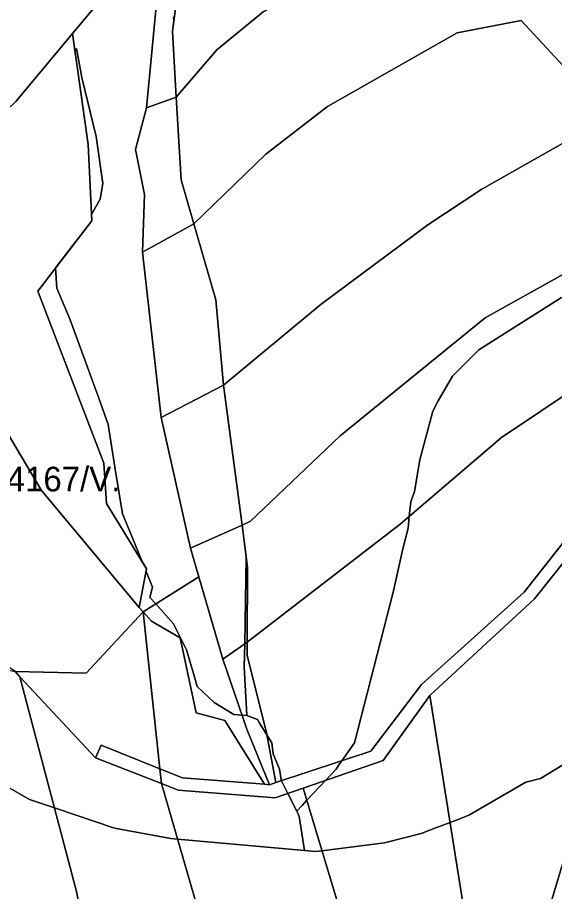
# Model space of a CAD drawing. Extents: x -502026 to -497664, y -1143484 to -1138019.
# Drawn here: x -499892.7 to -499718.6, y -1138993.9 to -1138710.6 of the extents above; entities that cross this region are included whole.
import ezdxf

# ---------------------------------------------------------------- set-up
doc = ezdxf.new("R2010")
doc.units = 0
for name, color, linetype in [('37', 7, 'Continuous'), ('43', 7, 'Continuous'), ('55', 7, 'Continuous'), ('62', 7, 'Continuous'), ('7', 7, 'Continuous')]:
    doc.layers.add(name, color=color, linetype=linetype)

msp = doc.modelspace()

# ---------------------------------------------------------------- linework, layer by layer
at = {"layer": '37'}
for points in [[(-499624.19, -1138623.47), (-499697.07, -1138662.14), (-499715.47, -1138666.65), (-499778.38, -1138690.2), (-499812.98, -1138708.74), (-499828.03, -1138721.09), (-499841.22, -1138736.39), (-499842.46, -1138715.08), (-499840.59, -1138700.98), (-499826.55, -1138669.42), (-499786.16, -1138649.02), (-499741.11, -1138634.19), (-499707.24, -1138629.85), (-499653.4, -1138608.06), (-499638.95, -1138599.65)], [(-499584.72, -1138701.93), (-499647.14, -1138735.95), (-499688.61, -1138754.3), (-499700.38, -1138742.85), (-499700.56, -1138742.65), (-499729.36, -1138711.56), (-499750.17, -1138715.52), (-499792.14, -1138739.41), (-499812.14, -1138754.89), (-499835.52, -1138777.51), (-499839.65, -1138763.23), (-499841.22, -1138736.39), (-499828.03, -1138721.09), (-499812.98, -1138708.74), (-499778.38, -1138690.2), (-499715.47, -1138666.65), (-499697.07, -1138662.14), (-499624.19, -1138623.47), (-499605.59, -1138653.48), (-499597.17, -1138655.53), (-499535.12, -1138622.58), (-499555.94, -1138687.68), (-499558.61, -1138690.15), (-499573.23, -1138697.97)], [(-499700.56, -1138742.65), (-499742.16, -1138766.28), (-499759.69, -1138777.83), (-499794.21, -1138803.47), (-499825.87, -1138829.77), (-499828.42, -1138802.06), (-499835.52, -1138777.51), (-499812.14, -1138754.89), (-499792.14, -1138739.41), (-499750.17, -1138715.52), (-499729.36, -1138711.56)], [(-499688.61, -1138754.3), (-499686.59, -1138756.26), (-499686.17, -1138759.35), (-499683.91, -1138775.8), (-499683.87, -1138776.05), (-499741.05, -1138807.99), (-499788.02, -1138846.17), (-499817.14, -1138873.87), (-499819.87, -1138875.19), (-499825.87, -1138829.77), (-499794.21, -1138803.47), (-499759.69, -1138777.83), (-499742.16, -1138766.28), (-499700.56, -1138742.65), (-499700.38, -1138742.85)], [(-499677.97, -1138812.1), (-499697.49, -1138821.17), (-499735.75, -1138846.76), (-499768.66, -1138874.79), (-499818.19, -1138913.08), (-499818.08, -1138888.78), (-499819.87, -1138875.19), (-499817.14, -1138873.87), (-499788.02, -1138846.17), (-499741.05, -1138807.99), (-499683.87, -1138776.05)], [(-499672.73, -1138826.19), (-499728.38, -1138896.85), (-499761.65, -1138926.83), (-499778.12, -1138948.42), (-499808.88, -1138958.63), (-499811.95, -1138942.47), (-499818.21, -1138917.28), (-499818.19, -1138913.08), (-499768.66, -1138874.79), (-499735.75, -1138846.76), (-499697.49, -1138821.17), (-499677.97, -1138812.1)], [(-499692.22, -1139026.74), (-499706.34, -1139073.94), (-499740.09, -1139074.1), (-499740.7, -1139066.99), (-499704.64, -1138947.61), (-499698.3, -1138985.62)]]:
    msp.add_lwpolyline(points, close=True, dxfattribs=at)
at = {"layer": '43'}
msp.add_lwpolyline([(-499902.54, -1138656.11), (-499880.58, -1138648.07), (-499846.81, -1138644), (-499831.31, -1138625.84), (-499798.18, -1138628.43), (-499780.24, -1138632.61), (-499752.34, -1138635.48), (-499793.82, -1138640.76), (-499822.42, -1138652.25), (-499843.96, -1138678.89), (-499874.85, -1138715.81), (-499893.13, -1138737.65)], dxfattribs=at)
for points in [[(-499840.59, -1138700.98), (-499842.46, -1138715.08), (-499841.22, -1138736.39), (-499850.82, -1138739.83), (-499847.44, -1138703.59), (-499843.96, -1138678.89), (-499822.42, -1138652.25), (-499838.76, -1138687.12)], [(-499850.82, -1138739.83), (-499854.46, -1138753.4), (-499851.53, -1138767.96), (-499852.16, -1138786.6), (-499846.16, -1138840.24), (-499836.59, -1138882.65), (-499833.88, -1138891.94), (-499851.98, -1138903.25), (-499853.25, -1138901.83), (-499850.82, -1138889.32), (-499863.78, -1138868.14), (-499864.68, -1138855.11), (-499886.12, -1138799.3), (-499868.63, -1138776.44), (-499869.78, -1138751.79), (-499874.85, -1138715.81), (-499843.96, -1138678.89), (-499847.44, -1138703.59)], [(-499835.52, -1138777.51), (-499852.16, -1138786.6), (-499851.53, -1138767.96), (-499854.46, -1138753.4), (-499850.82, -1138739.83), (-499841.22, -1138736.39), (-499839.65, -1138763.23)], [(-499825.87, -1138829.77), (-499846.16, -1138840.24), (-499852.16, -1138786.6), (-499835.52, -1138777.51), (-499828.42, -1138802.06)], [(-499819.87, -1138875.19), (-499836.59, -1138882.65), (-499846.16, -1138840.24), (-499825.87, -1138829.77)], [(-499818.19, -1138913.08), (-499826.12, -1138918.58), (-499833.88, -1138891.94), (-499836.59, -1138882.65), (-499819.87, -1138875.19), (-499818.08, -1138888.78)], [(-499826.12, -1138918.58), (-499818.34, -1138941.27), (-499810.93, -1138959.31), (-499812.62, -1138959.18), (-499825.48, -1138938.52), (-499834.8, -1138935.97), (-499839.91, -1138911.67), (-499849.23, -1138906.3), (-499851.98, -1138903.25), (-499833.88, -1138891.94)], [(-499808.88, -1138958.63), (-499810.93, -1138959.31), (-499818.34, -1138941.27), (-499826.12, -1138918.58), (-499818.19, -1138913.08), (-499818.21, -1138917.28), (-499811.95, -1138942.47)]]:
    msp.add_lwpolyline(points, close=True, dxfattribs=at)
at = {"layer": '55'}
msp.add_lwpolyline([(-499714.87, -1138886.33), (-499725.1, -1138899.04), (-499758.97, -1138930.35), (-499774.17, -1138951.42), (-499800.05, -1138960.4), (-499809.14, -1138963.55), (-499840.61, -1138961.03), (-499846.04, -1138958.92), (-499846.55, -1138954.13), (-499839.14, -1138957.13), (-499812.62, -1138959.18), (-499810.93, -1138959.31), (-499808.88, -1138958.63), (-499778.12, -1138948.42), (-499761.65, -1138926.83), (-499728.38, -1138896.85), (-499672.73, -1138826.19)], dxfattribs=at)
at = {"layer": '62'}
for points in [[(-499842.09, -1138710.37), (-499842, -1138711.59), (-499842.46, -1138715.08), (-499841.22, -1138736.39), (-499839.65, -1138763.23), (-499835.52, -1138777.51), (-499828.42, -1138802.06), (-499825.87, -1138829.77), (-499819.87, -1138875.19), (-499818.5, -1138885.58), (-499819.02, -1138913.65), (-499819.16, -1138921.12), (-499818.31, -1138936.87), (-499819.89, -1138936.73), (-499822.56, -1138936.5), (-499828.94, -1138932.62), (-499834.44, -1138927.5), (-499835.65, -1138923.27), (-499837.84, -1138915.62), (-499842.09, -1138907.12), (-499847.89, -1138900.69), (-499849.75, -1138898.62), (-499848.91, -1138895.25), (-499850.99, -1138890.18), (-499850.82, -1138889.32), (-499852.4, -1138886.73), (-499855.55, -1138879.07), (-499858.66, -1138871.5), (-499861, -1138857), (-499863.34, -1138842.5), (-499866.31, -1138834), (-499875.66, -1138808.62), (-499879.91, -1138798.37), (-499880.34, -1138791.74), (-499868.63, -1138776.44), (-499868.72, -1138774.48), (-499865.91, -1138769.5), (-499865.03, -1138764.37), (-499867.16, -1138749.12), (-499871.84, -1138730), (-499873.53, -1138720.62), (-499874.09, -1138721.24), (-499874.85, -1138715.81), (-499893.13, -1138737.65)], [(-499716.34, -1138801.37), (-499743.09, -1138818.37), (-499751.59, -1138826.87), (-499756.28, -1138834.87), (-499757.97, -1138838.25), (-499762.22, -1138854), (-499763.94, -1138864.25), (-499765.19, -1138867.62), (-499765.66, -1138872.24), (-499766.06, -1138876.12), (-499767.75, -1138882.87), (-499770.72, -1138896.5), (-499783.47, -1138945.75), (-499787.51, -1138951.54), (-499788.47, -1138952.91), (-499789.41, -1138954.25), (-499792.81, -1138957.89), (-499798.86, -1138964.36), (-499800.42, -1138966.01), (-499802.16, -1138967.87), (-499805.05, -1138962.13), (-499806.01, -1138960.22), (-499807.1, -1138958.04), (-499807.25, -1138957.75), (-499807.69, -1138954.25), (-499809.81, -1138949.25), (-499810.25, -1138945.75), (-499811.81, -1138943.19), (-499814.32, -1138939.09), (-499814.91, -1138938.12), (-499818.31, -1138936.87), (-499819.16, -1138921.12), (-499819.02, -1138913.65), (-499818.5, -1138885.58), (-499819.87, -1138875.19), (-499825.87, -1138829.77), (-499828.42, -1138802.06), (-499835.52, -1138777.51), (-499839.65, -1138763.23), (-499841.22, -1138736.39), (-499842.46, -1138715.08), (-499842, -1138711.59), (-499842.09, -1138710.37)], [(-499893.13, -1138737.65), (-499874.85, -1138715.81), (-499874.09, -1138721.24), (-499873.53, -1138720.62), (-499871.84, -1138730), (-499867.16, -1138749.12), (-499865.03, -1138764.37), (-499865.91, -1138769.5), (-499868.72, -1138774.48), (-499868.63, -1138776.44), (-499880.34, -1138791.74), (-499879.91, -1138798.37), (-499875.66, -1138808.62), (-499866.31, -1138834), (-499863.34, -1138842.5), (-499861, -1138857), (-499858.66, -1138871.5), (-499855.55, -1138879.07), (-499852.4, -1138886.73), (-499850.82, -1138889.32), (-499850.99, -1138890.18), (-499848.91, -1138895.25), (-499849.75, -1138898.62), (-499847.89, -1138900.69), (-499842.09, -1138907.12), (-499837.84, -1138915.62), (-499835.65, -1138923.27), (-499834.44, -1138927.5), (-499828.94, -1138932.62), (-499822.56, -1138936.5), (-499819.89, -1138936.73), (-499818.31, -1138936.87), (-499814.91, -1138938.12), (-499814.32, -1138939.09), (-499811.81, -1138943.19), (-499810.25, -1138945.75), (-499809.81, -1138949.25), (-499807.69, -1138954.25), (-499807.25, -1138957.75), (-499807.1, -1138958.04), (-499806.01, -1138960.22), (-499805.05, -1138962.13), (-499802.16, -1138967.87), (-499801.93, -1138968.33), (-499801.31, -1138969.62), (-499799.62, -1138980.62), (-499840.81, -1138976.94), (-499842.94, -1138976.75), (-499844.83, -1138976.4), (-499861.22, -1138973.37), (-499880.73, -1138966.84), (-499888.84, -1138964.12), (-499908.81, -1138952.62)], [(-499711.25, -1138950), (-499723.12, -1138957.25), (-499727.81, -1138958.5), (-499746.09, -1138969.12), (-499748.76, -1138970.14), (-499752.41, -1138971.54), (-499757.39, -1138973.43), (-499761.81, -1138975.12), (-499773.69, -1138978.12), (-499793.96, -1138980.71), (-499796.22, -1138981), (-499799.62, -1138980.62), (-499801.31, -1138969.62), (-499801.93, -1138968.33), (-499802.16, -1138967.87), (-499800.42, -1138966.01), (-499798.86, -1138964.36), (-499792.81, -1138957.89), (-499789.41, -1138954.25), (-499788.47, -1138952.91), (-499787.51, -1138951.54), (-499783.47, -1138945.75), (-499770.72, -1138896.5), (-499767.75, -1138882.87), (-499766.06, -1138876.12), (-499765.66, -1138872.24), (-499765.19, -1138867.62), (-499763.94, -1138864.25), (-499762.22, -1138854), (-499757.97, -1138838.25), (-499756.28, -1138834.87), (-499751.59, -1138826.87), (-499743.09, -1138818.37), (-499716.34, -1138801.37)], [(-499908.81, -1138952.62), (-499888.84, -1138964.12), (-499880.73, -1138966.84), (-499861.22, -1138973.37), (-499844.83, -1138976.4), (-499842.94, -1138976.75), (-499840.81, -1138976.94), (-499799.62, -1138980.62), (-499796.22, -1138981), (-499793.96, -1138980.71), (-499773.69, -1138978.12), (-499761.81, -1138975.12), (-499757.39, -1138973.43), (-499752.41, -1138971.54), (-499748.76, -1138970.14), (-499746.09, -1138969.12), (-499727.81, -1138958.5), (-499723.12, -1138957.25), (-499711.25, -1138950)]]:
    msp.add_lwpolyline(points, dxfattribs=at)
at = {"layer": '7'}
for points in [[(-499853.25, -1138901.83), (-499884.89, -1138863.95), (-499914.57, -1138814.1), (-499929.19, -1138771.1), (-499925.18, -1138768.49), (-499893.13, -1138737.65), (-499874.85, -1138715.81), (-499869.78, -1138751.79), (-499868.63, -1138776.44), (-499886.12, -1138799.3), (-499864.68, -1138855.11), (-499863.78, -1138868.14), (-499850.82, -1138889.32)], [(-499853.25, -1138901.83), (-499851.98, -1138903.25), (-499870.45, -1138923.16), (-499893.5, -1138922.59), (-499918.38, -1138905.54), (-499927.1, -1138891.77), (-499935.99, -1138876.45), (-499946.46, -1138854.1), (-499956.62, -1138818.86), (-499961.38, -1138796.48), (-499962.64, -1138786.5), (-499944.97, -1138781.37), (-499929.19, -1138771.1), (-499914.57, -1138814.1), (-499884.89, -1138863.95)], [(-499704.64, -1138947.61), (-499740.7, -1139066.99), (-499744.7, -1139019.96), (-499758.97, -1138930.35), (-499725.1, -1138899.04), (-499714.87, -1138886.33)], [(-499846.55, -1138954.13), (-499865.51, -1138946.47), (-499867.44, -1138950.63), (-499891.9, -1138924.31), (-499893.5, -1138922.59), (-499870.45, -1138923.16), (-499851.98, -1138903.25)], [(-499812.62, -1138959.18), (-499839.14, -1138957.13), (-499846.55, -1138954.13), (-499851.98, -1138903.25), (-499849.23, -1138906.3), (-499839.91, -1138911.67), (-499834.8, -1138935.97), (-499825.48, -1138938.52)], [(-499893.5, -1138922.59), (-499891.9, -1138924.31), (-499873.61, -1138993.97), (-499858.12, -1139072.27), (-499885.93, -1139069.02), (-499920.58, -1139058.73), (-499944.68, -1138922.07), (-499939.62, -1138922.22), (-499913.44, -1138918.25)], [(-499867.44, -1138950.63), (-499846.04, -1138958.92), (-499830.54, -1139012.34), (-499816.32, -1139077.2), (-499858.12, -1139072.27), (-499873.61, -1138993.97), (-499891.9, -1138924.31)], [(-499740.7, -1139066.99), (-499742.88, -1139074.2), (-499771.2, -1139075.21), (-499783.57, -1139015.36), (-499800.05, -1138960.4), (-499774.17, -1138951.42), (-499758.97, -1138930.35), (-499744.7, -1139019.96)], [(-499846.55, -1138954.13), (-499846.04, -1138958.92), (-499867.44, -1138950.63), (-499865.51, -1138946.47)], [(-499800.05, -1138960.4), (-499783.57, -1139015.36), (-499771.2, -1139075.21), (-499816.32, -1139077.2), (-499830.54, -1139012.34), (-499846.04, -1138958.92), (-499840.61, -1138961.03), (-499809.14, -1138963.55)]]:
    msp.add_lwpolyline(points, close=True, dxfattribs=at)

# ---------------------------------------------------------------- texts
at = {"layer": '62'}
msp.add_text('64167/V.', height=8, dxfattribs=at).set_placement((-499902.16, -1138864.21))

doc.saveas('drawing.dxf')
